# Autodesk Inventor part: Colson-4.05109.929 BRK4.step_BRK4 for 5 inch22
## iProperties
Created: 2010-10
Part Number: Colson-4.05109.929 BRK4.step_BRK4 for 5 inch22
Document SubType Name: Modeling
Designer: Administrator
Density: 1.06 g/cm^3
Material: ABS Plastic
Mass: 106.736 g
Surface Area: 495.754 cm^2
Volume: 100.694 cm^3
Author: Administrator
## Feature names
1. Base1
